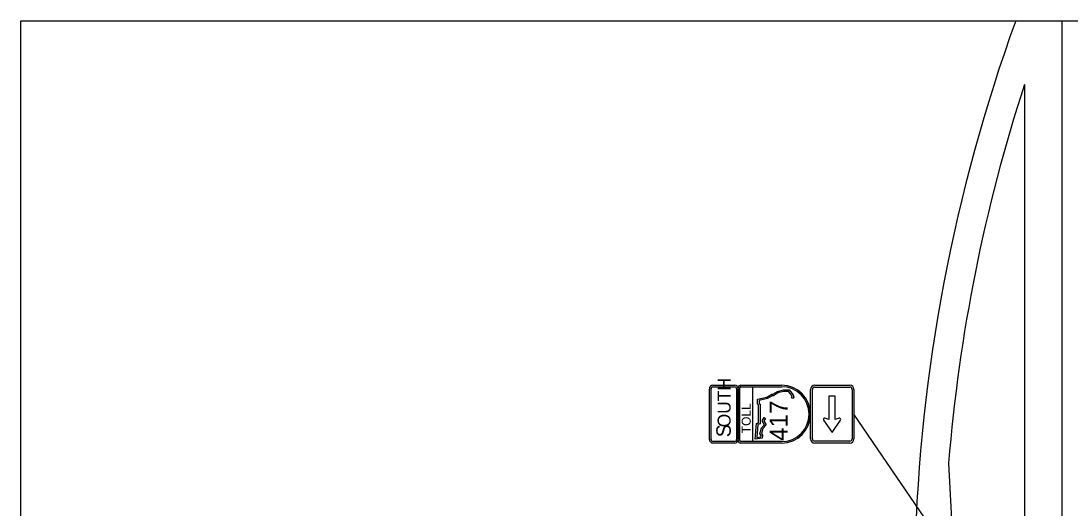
# Model space of a CAD drawing. Extents: x -830008.4 to -829992.7, y 1290284.1 to 1290294.4.
# Drawn here: x -830007.47 to -830000.13, y 1290290.81 to 1290294.23 of the extents above; entities that cross this region are included whole.
import ezdxf

# ---------------------------------------------------------------- set-up
doc = ezdxf.new("R2010")
doc.units = 0
for name, color, linetype in [('1', 7, 'Continuous'), ('SheetBorder_dp', 7, 'Continuous'), ('SheetLines_dp', 7, 'Continuous')]:
    doc.layers.add(name, color=color, linetype=linetype)

msp = doc.modelspace()

# ---------------------------------------------------------------- linework, layer by layer
at = {"layer": '1'}
for p, q in [((-830000.1852, 1290294.228), (-830000.1852, 1290285.328)), ((-830000.448, 1290293.7828), (-830000.448, 1290288.446)), ((-830000.7731, 1290290.1996), (-830001.6415, 1290291.4727)), ((-830000.9789, 1290291.1282), (-830000.922, 1290290.0166))]:
    msp.add_line(p, q, dxfattribs=at)
for radius, start, end in [(11.8114, 160.03301, 178.50157), (11.6089, 161.99605, 175.38775)]:
    msp.add_arc((-829989.4075, 1290290.1947), radius, start, end, dxfattribs=at)
at = {"layer": 'SheetBorder_dp'}
for p, q in [((-830002.2504, 1290291.5919), (-830002.217, 1290291.6127)), ((-830002.217, 1290291.6127), (-830002.2086, 1290291.6127)), ((-830002.2086, 1290291.6127), (-830002.1776, 1290291.6315)), ((-830002.1734, 1290291.6217), (-830002.2056, 1290291.6021)), ((-830002.1776, 1290291.6315), (-830002.1352, 1290291.6431)), ((-830002.1338, 1290291.6325), (-830002.1734, 1290291.6217)), ((-830002.1352, 1290291.6431), (-830002.0956, 1290291.6431)), ((-830002.1006, 1290291.6325), (-830002.1338, 1290291.6325)), ((-830002.077, 1290291.6037), (-830002.1006, 1290291.6325)), ((-830002.0956, 1290291.6431), (-830002.0673, 1290291.6085)), ((-830002.0673, 1290291.6085), (-830002.0634, 1290291.5921)), ((-830002.3162, 1290291.5766), (-830002.2504, 1290291.5919)), ((-830002.3162, 1290291.5428), (-830002.3162, 1290291.5766)), ((-830002.3092, 1290291.5381), (-830002.3162, 1290291.5428)), ((-830002.3092, 1290291.4127), (-830002.3092, 1290291.5381)), ((-830002.2464, 1290291.582), (-830002.3056, 1290291.5682)), ((-830002.3056, 1290291.5682), (-830002.3056, 1290291.5484)), ((-830002.3056, 1290291.5484), (-830002.2987, 1290291.5437)), ((-830002.2987, 1290291.5437), (-830002.2987, 1290291.4055)), ((-830002.214, 1290291.6021), (-830002.2464, 1290291.582)), ((-830002.2056, 1290291.6021), (-830002.214, 1290291.6021)), ((-830002.0793, 1290291.5877), (-830002.0747, 1290291.5942)), ((-830002.0706, 1290291.5817), (-830002.0793, 1290291.5877)), ((-830002.0747, 1290291.5942), (-830002.077, 1290291.6037)), ((-830002.0634, 1290291.5921), (-830002.0706, 1290291.5817)), ((-830001.8177, 1290291.5985), (-830001.8177, 1290291.4361)), ((-830001.7722, 1290291.5985), (-830001.8177, 1290291.5985)), ((-830001.7722, 1290291.4361), (-830001.7722, 1290291.5985)), ((-830002.3334, 1290291.2972), (-830002.3249, 1290291.4065)), ((-830002.3249, 1290291.4065), (-830002.3092, 1290291.4127)), ((-830002.3149, 1290291.3991), (-830002.3218, 1290291.3097)), ((-830002.2987, 1290291.4055), (-830002.3149, 1290291.3991)), ((-830002.2878, 1290291.3775), (-830002.2686, 1290291.3982)), ((-830002.2851, 1290291.4262), (-830002.2697, 1290291.4491)), ((-830002.2686, 1290291.3982), (-830002.2851, 1290291.4262)), ((-830002.2556, 1290291.3967), (-830002.2785, 1290291.372)), ((-830002.2609, 1290291.4432), (-830002.2727, 1290291.4258)), ((-830002.2727, 1290291.4258), (-830002.2556, 1290291.3967)), ((-830002.2697, 1290291.4491), (-830002.2609, 1290291.4432)), ((-830001.8542, 1290291.4309), (-830001.7949, 1290291.3447)), ((-830001.8177, 1290291.4361), (-830001.8445, 1290291.4441)), ((-830001.7949, 1290291.3447), (-830001.7357, 1290291.4309)), ((-830001.7454, 1290291.4441), (-830001.7722, 1290291.4361)), ((-830002.3218, 1290291.3097), (-830002.2928, 1290291.3142)), ((-830002.3015, 1290291.3353), (-830002.2878, 1290291.3775)), ((-830002.2918, 1290291.3228), (-830002.3015, 1290291.3353)), ((-830002.2928, 1290291.3142), (-830002.2918, 1290291.3228)), ((-830002.2785, 1290291.372), (-830002.2898, 1290291.3374)), ((-830002.2898, 1290291.3374), (-830002.2808, 1290291.3259)), ((-830002.2808, 1290291.3259), (-830002.2833, 1290291.305)), ((-830002.2833, 1290291.305), (-830002.3334, 1290291.2972))]:
    msp.add_line(p, q, dxfattribs=at)
for points in [[(-830002.654, 1290291.2955), (-830002.654, 1290291.6499)], [(-830002.6424, 1290291.2955), (-830002.6424, 1290291.6499)], [(-830002.6287, 1290291.6752), (-830002.4768, 1290291.6752)], [(-830002.6287, 1290291.6636), (-830002.4768, 1290291.6636)], [(-830002.4631, 1290291.6499), (-830002.4631, 1290291.2955)], [(-830002.4515, 1290291.2871), (-830002.4515, 1290291.6583)], [(-830002.4515, 1290291.6499), (-830002.4515, 1290291.2955)], [(-830002.4414, 1290291.2871), (-830002.4414, 1290291.6583)], [(-830002.4346, 1290291.6752), (-830002.1477, 1290291.6752)], [(-830002.4346, 1290291.6651), (-830002.1477, 1290291.6651)], [(-830002.3502, 1290291.2803), (-830002.3502, 1290291.6651)], [(-830001.9452, 1290291.2991), (-830001.9452, 1290291.6463)], [(-830001.932, 1290291.2991), (-830001.932, 1290291.6463)], [(-830001.9163, 1290291.6752), (-830001.6704, 1290291.6752)], [(-830001.9163, 1290291.6619), (-830001.6704, 1290291.6619)], [(-830001.6548, 1290291.6463), (-830001.6548, 1290291.2991)], [(-830001.6415, 1290291.6463), (-830001.6415, 1290291.2991)], [(-830002.4768, 1290291.2818), (-830002.6287, 1290291.2818)], [(-830002.4768, 1290291.2702), (-830002.6287, 1290291.2702)], [(-830002.1477, 1290291.2803), (-830002.4346, 1290291.2803)], [(-830002.1477, 1290291.2702), (-830002.4346, 1290291.2702)], [(-830001.6704, 1290291.2834), (-830001.9163, 1290291.2834)], [(-830001.6704, 1290291.2702), (-830001.9163, 1290291.2702)]]:
    msp.add_lwpolyline(points, dxfattribs=at)
for centre, radius, start, end in [((-830002.6287, 1290291.6499), 0.0253, 90, 180), ((-830002.6287, 1290291.6499), 0.0137, 90, 180), ((-830002.4768, 1290291.6499), 0.0253, 0, 90), ((-830002.4768, 1290291.6499), 0.0137, 0, 90), ((-830002.4346, 1290291.6583), 0.0169, 90, 180), ((-830002.4346, 1290291.6583), 0.00675, 90, 180), ((-830002.1477, 1290291.4727), 0.2025, 270, 90), ((-830002.1477, 1290291.4727), 0.1924, 270, 90), ((-830001.9163, 1290291.6463), 0.0289, 90, 180), ((-830001.9163, 1290291.6463), 0.0157, 90.0544, 180), ((-830001.6704, 1290291.6463), 0.0289, 0, 90), ((-830001.6704, 1290291.6463), 0.0157, 0, 90), ((-830001.847, 1290291.4358), 0.00868, 73.35571, 214.48807), ((-830001.7429, 1290291.4358), 0.00868, 325.51192, 106.64431), ((-830002.6287, 1290291.2955), 0.0253, 180, 270), ((-830002.6287, 1290291.2955), 0.0137, 180, 270), ((-830002.4768, 1290291.2955), 0.0253, 270, 360), ((-830002.4768, 1290291.2955), 0.0137, 270, 360), ((-830002.4346, 1290291.2871), 0.0169, 180, 270), ((-830002.4346, 1290291.2871), 0.00675, 180, 270), ((-830001.9163, 1290291.2991), 0.0289, 180, 270), ((-830001.9163, 1290291.2991), 0.0157, 180, 269.9456), ((-830001.6704, 1290291.2991), 0.0289, 270, 360), ((-830001.6704, 1290291.2991), 0.0157, 270, 360)]:
    msp.add_arc(centre, radius, start, end, dxfattribs=at)
at = {"layer": 'SheetLines_dp'}
msp.add_lwpolyline([(-830007.4742, 1290294.228), (-829992.7742, 1290294.228), (-829992.7742, 1290285.328), (-830007.4742, 1290285.328)], close=True, dxfattribs=at)

# ---------------------------------------------------------------- texts
at = {"layer": 'SheetBorder_dp'}
for s, height, p in [('OUTH', 0.09113, (-830002.5049, 1290291.3803)), ('TOLL', 0.06328, (-830002.3642, 1290291.3383)), ('417', 0.12656, (-830002.1055, 1290291.2853)), ('S', 0.1013, (-830002.5038, 1290291.311))]:
    msp.add_text(s, height=height, rotation=90, dxfattribs=at).set_placement(p)

doc.saveas('drawing.dxf')
